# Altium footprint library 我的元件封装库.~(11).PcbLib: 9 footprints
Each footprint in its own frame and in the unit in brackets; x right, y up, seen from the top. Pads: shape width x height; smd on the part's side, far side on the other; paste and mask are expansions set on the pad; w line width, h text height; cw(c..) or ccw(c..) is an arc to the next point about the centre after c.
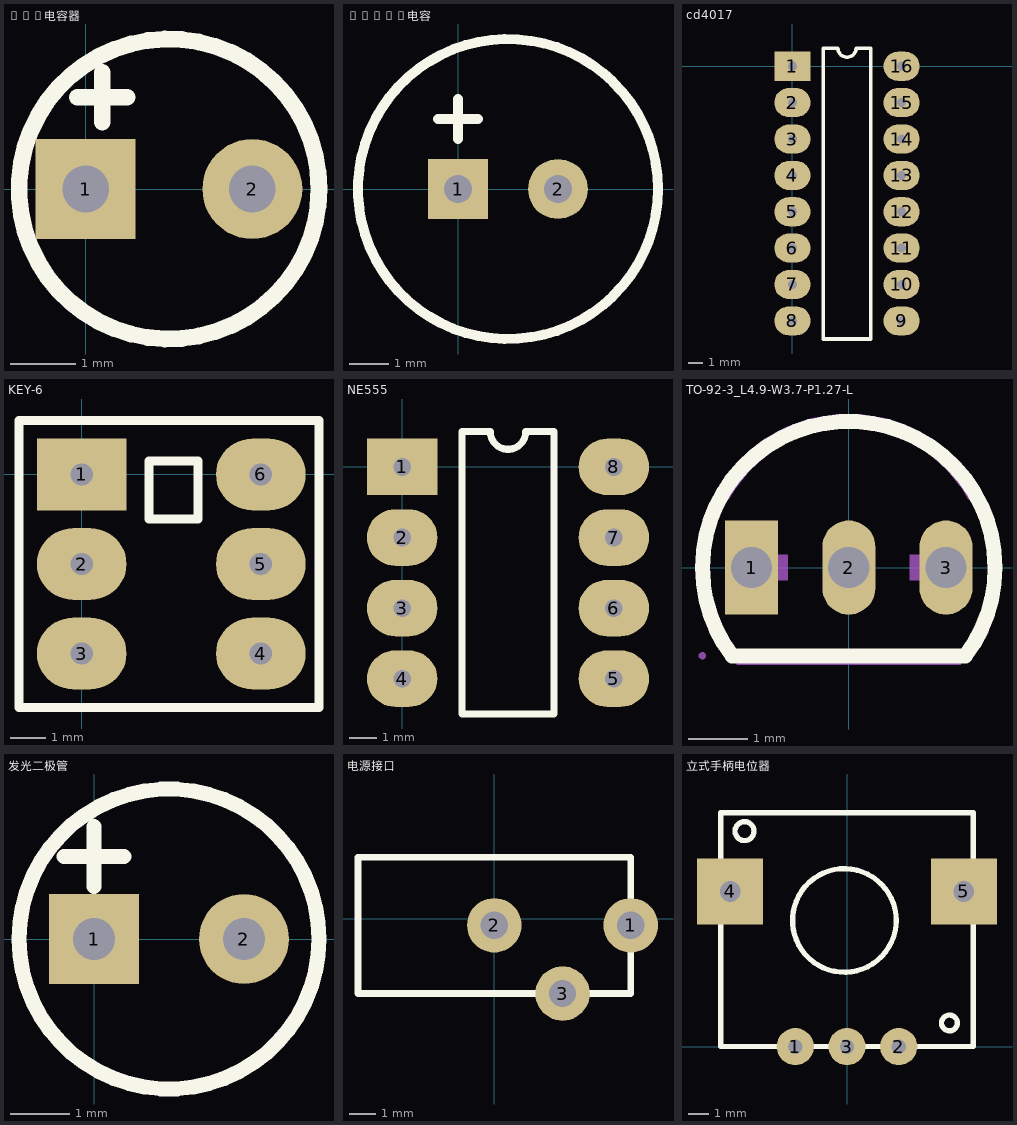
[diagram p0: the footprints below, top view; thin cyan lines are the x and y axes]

## 1uF电容器 [mil]
pads (2):
  rect 60x60 hole 28: 1(0,0)
  round 60 hole 28: 2(100,0)
Top Overlay:
  circle w10: c50,0 r90
  lines w10: -5,55 25,55 ; 10,40 10,70

## 220uF电容 [mil]
pads (2):
  rect 60x60 hole 28: 1(0,0)
  round 60 hole 28: 2(100,0)
Top Overlay:
  circle w10: c50,0 r150
  lines w10: -20,70 20,70 ; 0,50 0,90

## cd4017 [mil]
pads (16):
  rect 100x80 hole 25: 1(0,0)
  oval 100x80 hole 25: 2(0,-100) 3(0,-200) 4(0,-300) 5(0,-400) 6(0,-500) 7(0,-600) 8(0,-700) 9(300,-700) 10(300,-600) 11(300,-500) 12(300,-400) 13(300,-300) 14(300,-200) 15(300,-100) 16(300,0)
Top Overlay:
  lines w10: 85,-750 85,50 125,50 ccw(c150,50) 175,50 215,50 215,-750 85,-750

## KEY-6 [mil]
pads (6):
  rect 100x80 hole 25: 1(0,0)
  oval 100x80 hole 25: 2(0,-100) 3(0,-200) 4(200,-200) 5(200,-100) 6(200,0)
Top Overlay:
  lines w10: -70,-260 265,-260 265,60 -70,60 -70,-260 ; 75,-50 75,15 130,15 130,-50 75,-50

## NE555 [mil]
pads (8):
  rect 100x80 hole 25: 1(0,0)
  oval 100x80 hole 25: 2(0,-100) 3(0,-200) 4(0,-300) 5(300,-300) 6(300,-200) 7(300,-100) 8(300,0)
Top Overlay:
  lines w10: 85,-350 85,50 125,50 ccw(c150,50) 175,50 215,50 215,-350 85,-350

## TO-92-3_L4.9-W3.7-P1.27-L [mm]
pads (3):
  rect 0.9x1.6 hole 0.7: 1(-1.651,0)
  oval 0.9x1.6 hole 0.7: 2(0,0) 3(1.651,0)
Top Overlay:
  lines w0.254: -1.981,-1.501 cw(c0,-0.003) 1.981,-1.501 ; -1.98,-1.5 1.98,-1.5
Mechanical 6:
  region: -2.29,1.16 -2.036,1.16 -1.931,1.339 -1.674,1.664 -1.363,1.938 -1.007,2.152 -0.619,2.299 -0.211,2.373 0.203,2.373 0.611,2.299 0.999,2.152 1.355,1.938 1.666,1.664 1.923,1.339 2.028,1.16 2.282,1.16 2.155,1.414 2.041,1.596 1.754,1.917 1.418,2.185 1.041,2.393 0.635,2.535 0.211,2.607 -0.219,2.607 -0.643,2.535 -1.049,2.393 -1.426,2.185 -1.762,1.917 -2.049,1.596 -2.163,1.414
  region: -1.905,-1.397 1.905,-1.397 1.905,-1.651 -1.905,-1.651
Mechanical 15:
  region: 1.035,-0.22 1.035,0.22 1.505,0.22 1.505,-0.22
  region: -0.235,-0.22 -0.235,0.22 0.235,0.22 0.235,-0.22
  region: -1.505,-0.22 -1.505,0.22 -1.035,0.22 -1.035,-0.22
  region: -2.424,-1.5 -2.424,-1.475 -2.459,-1.44 -2.509,-1.44 -2.544,-1.475 -2.544,-1.5 -2.544,-1.525 -2.509,-1.56 -2.459,-1.56 -2.424,-1.525 -2.424,-1.5
  lines w0.051: -2.484,0 ccw(c-2.484,0.003) -2.481,0.003 -2.481,0.124 cw(c-0.127,0.124) -0.127,2.478 0.124,2.478 cw(c0.124,0.118) 2.484,0.118 2.484,0 2.456,-0.397 2.342,-0.795 2.189,-1.158 1.98,-1.5 -1.98,-1.5 -2.181,-1.156 -2.265,-0.985 -2.34,-0.791 -2.399,-0.598 -2.443,-0.405 -2.466,-0.207 -2.484,0

## 发光二极管 [mil]
pads (2):
  rect 60x60 hole 28: 1(0,0)
  round 60 hole 28: 2(100,0)
Top Overlay:
  circle w10: c50,0 r100
  lines w10: -20,55 20,55 ; 0,35 0,75

## 电源接口 [mil]
pads (3):
  round 80 hole 40: 1(200,-10) 2(0,-10) 3(100,-110)
Top Overlay:
  lines w10: -200,-110 -200,90 200,90 200,-110 -200,-110

## 立式手柄电位器 [mm]
pads (5):
  round 1.8 hole 0.7 square: 1(-2.5,0) 2(2.5,0) 3(0,0)
  rect 3.2x3.2 hole 1 square: 4(-5.65,7.5) 5(5.65,7.5)
Top Overlay:
  circle w0.254: c-0.127,6.096 r2.505
  circle w0.254: c-4.953,10.414 r0.458
  circle w0.254: c4.953,1.143 r0.381
  lines w0.254: 6.096,2.032 6.1,2.028 ; -6.1,0 6.1,0 6.1,11.3 -6.1,11.3 -6.1,0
